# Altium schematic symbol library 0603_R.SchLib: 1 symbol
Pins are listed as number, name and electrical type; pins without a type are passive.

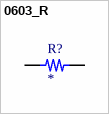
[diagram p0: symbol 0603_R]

## 0603_R
designator R?
footprint 0603
pins: 1, 2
